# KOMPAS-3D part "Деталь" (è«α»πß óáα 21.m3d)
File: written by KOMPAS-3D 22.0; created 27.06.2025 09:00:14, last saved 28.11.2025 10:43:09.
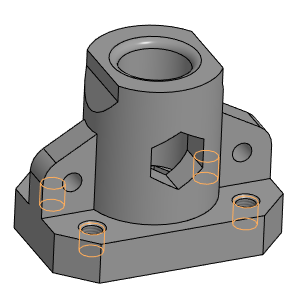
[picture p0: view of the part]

Document properties: Автор: alymovy@yandex.ru; Организация: HP; Полное имя файла: КорпусВариант 21.cdw

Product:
- Part/product: Деталь
    Материал: Полипропилен ГОСТ 26996-86 (density 900 kg/m3)
    Масса: 0.506228
    Форматы листов документа: A3

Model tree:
1. Эскиз:1
2. Элемент выдавливания:1
     Расстояние 1 = 25
3. Фаска:1  (with: Элемент выдавливания:1)
     Угол = 45; Длина 1 = 20; Длина 2 = 20
4. Эскиз:2  (with: Элемент выдавливания:1)
5. Элемент выдавливания:2
     Расстояние 1 = 85
6. Эскиз:3  (with: Фаска:1, Элемент выдавливания:2, Элемент выдавливания:1)
7. Ребро жесткости:1
     Толщина стенки 1 = 18; Толщина стенки 2 = 1
8. Зеркальный массив:1
9. Экземпляр ( 1 )
10. Экземпляр ( 2 )  (with: Ребро жесткости:1)
11. Эскиз:4  (with: Элемент выдавливания:2)
12. Элемент выдавливания:3
     Расстояние 1 = 47.5
13. Эскиз:5  (with: Элемент выдавливания:2)
14. Элемент выдавливания:4
     Расстояние 2 = 80
15. Эскиз:6  (with: Элемент выдавливания:4)
16. Элемент выдавливания:5
     Расстояние 2 = 30
17. Скругление:1  (with: Элемент выдавливания:4)
     Радиус = 5
18. Эскиз:7  (with: Ребро жесткости:1)
19. Элемент выдавливания:6
     Расстояние 1 = 38.5
20. Эскиз:8  (with: Элемент выдавливания:1, Элемент выдавливания:2)
21. Отверстие:1  (with: Элемент выдавливания:1, Ребро жесткости:1)  (labels: M14)
     Глубина выреза = 20; Диаметр отверстия = 11.8349; Угол конуса дна = 118; Расстояние 1 = -19; Расстояние 2 = 23; Диаметр зенковки = 15.8349; Глубина зенковки = 2; Угол зенковки = 90
22. M14  (labels: M14; cil0_24705-2004 coarse)
     Длина резьбы = 15; Шаг резьбы = 2; Номинальный диаметр резьбы = 14
23. Зеркальный массив:2  (with: Экземпляр ( 1 ), Экземпляр ( 2 ), Отверстие:1)
24. Зеркальный массив:3  (with: Экземпляр ( 1 ), Экземпляр ( 2 ), Зеркальный массив:2, Отверстие:1)
25. Экземпляр ( 2 )  (with: Отверстие:1)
